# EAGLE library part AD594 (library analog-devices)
ANALOG DEVICES
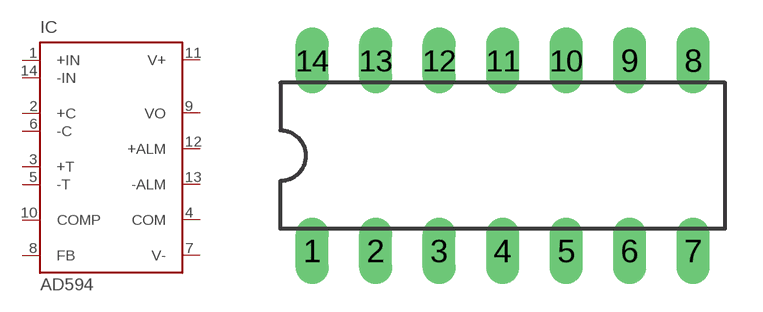
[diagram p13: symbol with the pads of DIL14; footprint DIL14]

Designator prefix IC

## AD594 (MF: ALTERA CORPORATION; MPN: AD594AQ; OC_FARNELL: 409182; OC_NEWARK: 05F7088)  [DIL14]
1  +IN  in
2  +C  in
3  +T  pas
4  COM  pwr
5  -T  pas
6  -C  in
7  V-  pwr
8  FB  pas
9  VO  out
10  COMP  pas
11  V+  pwr
12  +ALM  pas
13  -ALM  pas
14  -IN  in

## Footprint DIL14 (pad centres in mm)
Dual In Line Package
drill 0.813 long: 1 -7.62,-3.81; 2 -5.08,-3.81; 3 -2.54,-3.81; 4 0,-3.81; 5 2.54,-3.81; 6 5.08,-3.81; 7 7.62,-3.81; 8 7.62,3.81; 9 5.08,3.81; 10 2.54,3.81; 11 0,3.81; 12 -2.54,3.81; 13 -5.08,3.81; 14 -7.62,3.81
